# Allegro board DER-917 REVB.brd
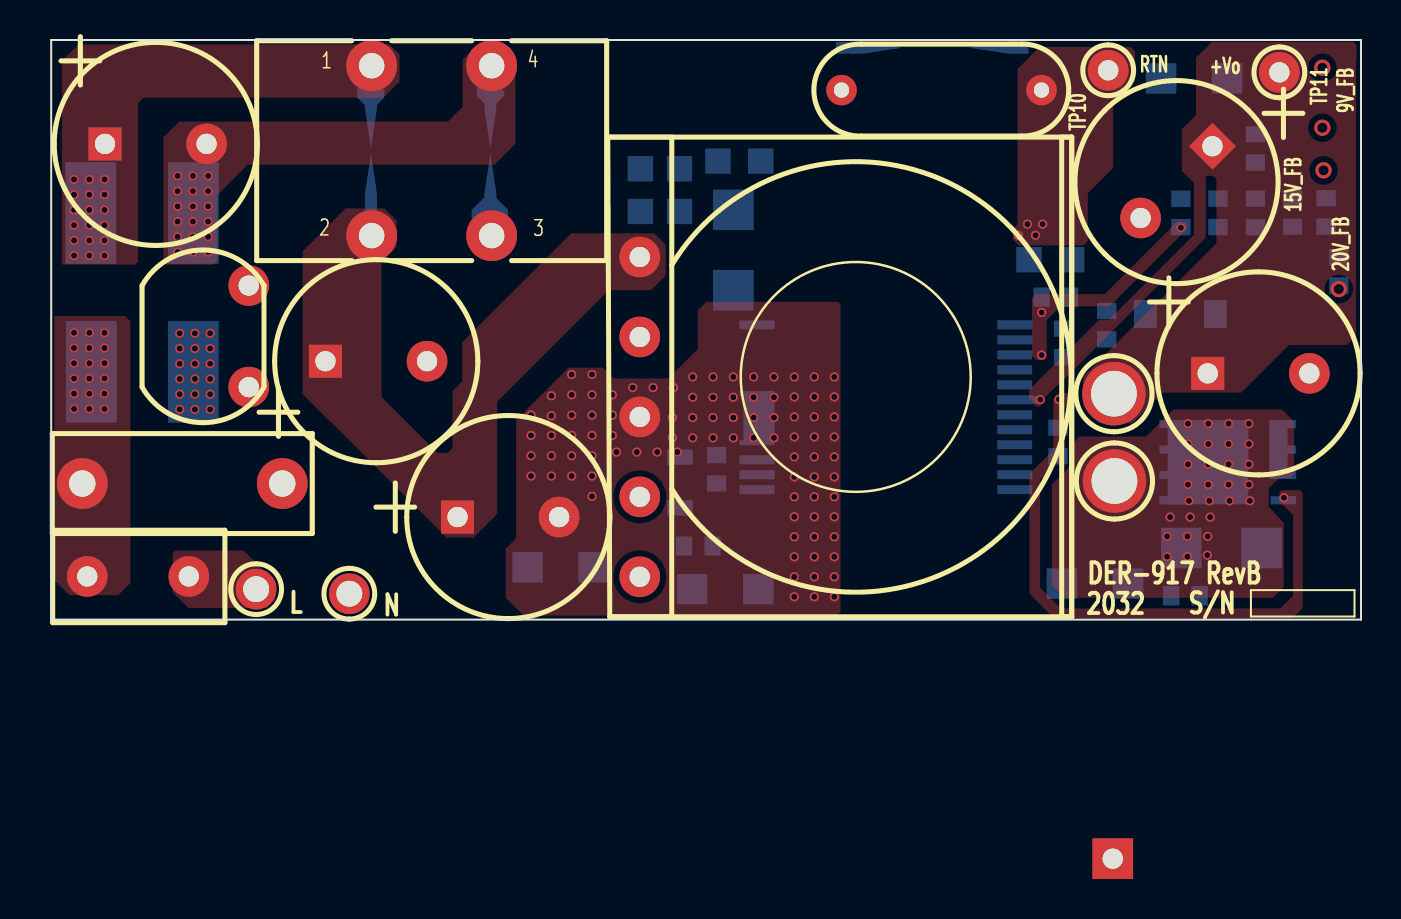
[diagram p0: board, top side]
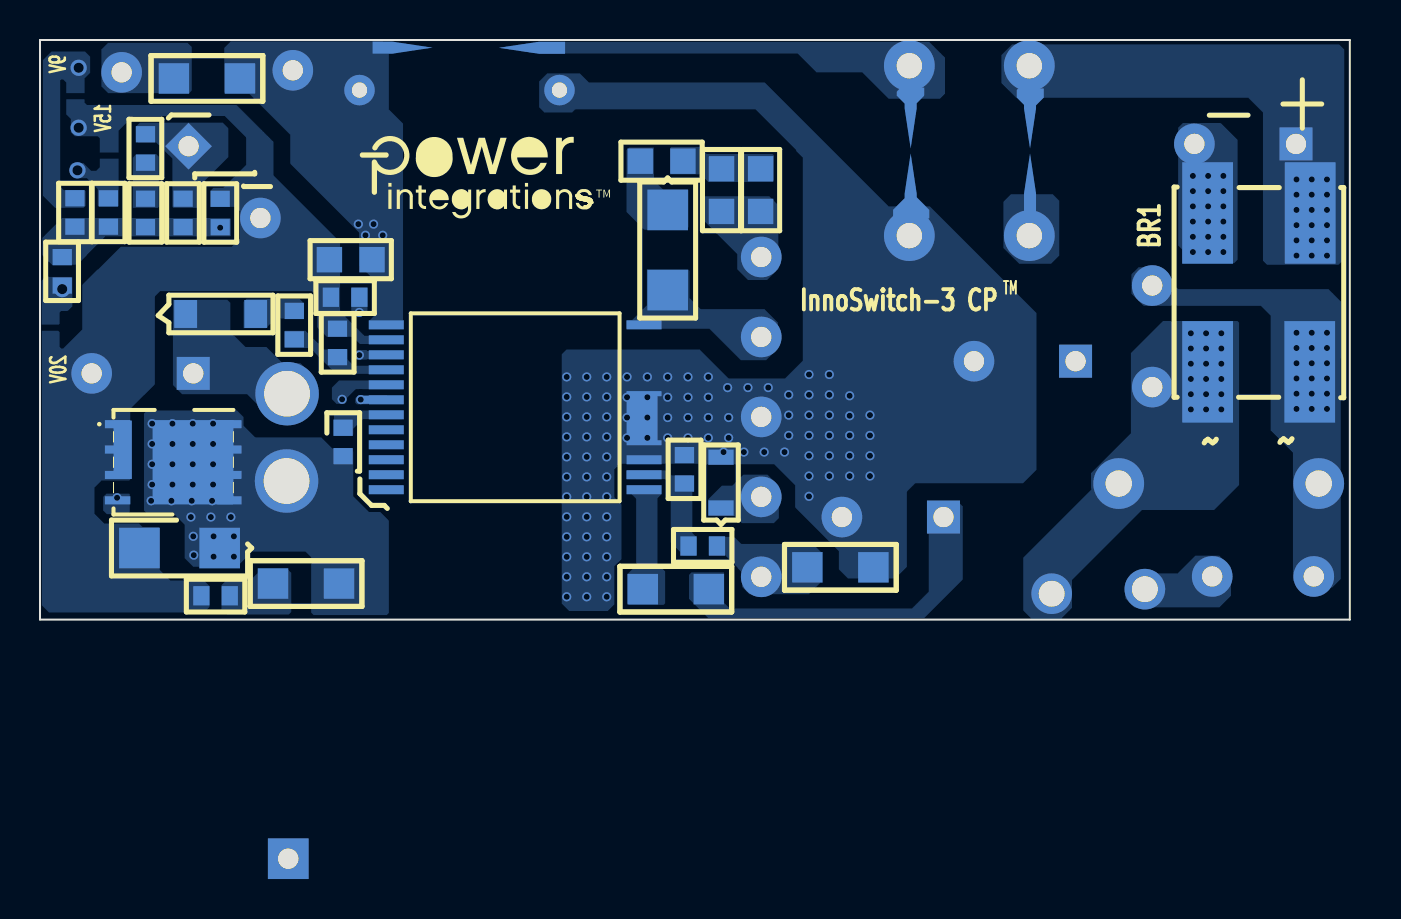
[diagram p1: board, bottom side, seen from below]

Outline 65.5 x 29 mm; copper layers: TOP, BOTTOM. Coordinates in mm from the lower left corner of the outline.
Outline path: 0,29 65.5,29 65.5,0 0,0 0,29

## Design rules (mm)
constraint set DEFAULT: min track width 0.508

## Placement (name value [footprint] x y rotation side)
BR1  Z4DGP406L-HF  [PI_SM_D_Z4D]  2.01 20.4 180 bottom
C1  0.1 uF  [PINPXCAPRAD5X13X11P1MM040]  11.56 6.81 180 top
C2  27 uF  [PIPOLCAPCYLD400LS200040]  20.32 5.13 0 top
C3  27 uF  [PIPOLCAPCYLD400LS200040]  13.72 12.93 0 top
C4  27 uF  [PIPOLCAPCYLD400LS200040]  2.69 23.8 0 top
C5  0.47 uF  [PISMC0603]  33.27 6.81 90 bottom
C6  10 uF  [PISMC1206]  27.13 2.62 180 bottom
C7  2200 pF  [PINPCAPRAD9P0D10P0LS030]  39.52 26.49 0 top
C8  2200 pF  [PISMC0603]  56.01 1.19 0 bottom
C9  2.2 uF  [PISMC0603]  50.62 13.13 90 bottom
C11  330 pF  [PISMC0603]  49.53 16.13 0 bottom
C12  47 nF  [PISMC0603]  60.22 21.06 270 bottom
C13  10 uF  [PISMC1206]  58.8 27.08 180 bottom
C14  390 uF  [PIPOLCAPCYLD400LS200040]  58.07 23.68 225 top
C15  390 uF  [PIPOLCAPCYLD400LS200040]  57.84 12.32 0 top
C18  470 pF  [PISMC0805]  29.46 20.42 90 bottom
D1  RS1J  [PISMDSMA]  34.11 20.5 270 bottom
D2  BAV21WS-7-F  [PISMSOD323]  31.45 5.59 90 bottom
D4  STPS2H100AY  [PISMDSMA]  56.52 3.58 0 bottom
F1  5 A  [PI_RST_MICROFUSE]  6.88 2.16 180 top
FL1  Hole_90  [PI_HOLE_70MIL]  53.14 11.28 0 top
FL2  Hole_90  [PI_HOLE_70MIL]  53.17 6.91 0 top
L1  18mH  [PI_CMC_18MH_SUMIDA]  16.03 27.71 0 top
NOREF  -  []  0 29 0 top
NOREF#2  -  []  -150.78 54.23 0 top
NOREF#3  -  []  65.5 0 90 top
NOREF#4  -  []  -228.6 -144.78 0 top
NOREF#5  -  []  49.43 23.95 180 bottom
Q3  SIR826ADP-T1-GE3  [PISMPQFN5X6B]  61.62 9.78 270 bottom
R5  30.1  [PISMR0805]  33.35 22.94 0 bottom
R8  24.9 k  [PISMR0603]  31.65 3.68 0 bottom
R10  47  [PISMR0603]  50.34 8.18 90 bottom
R13  0.0  [PISMR1206]  50.55 1.8 0 bottom
R14  100 k  [PISMR0603]  58.34 21.06 270 bottom
R15  33 K  [PISMR0603]  56.49 19.63 90 bottom
R16  0.005  [PISMR0805]  51.03 18.01 180 bottom
R19  2.2M  [PISMR1206]  35.36 1.52 180 bottom
R21  680 k  [PISMR0805]  31.42 20.42 90 bottom
R22  32.4 k  [PISMR0603]  63.75 19.66 90 bottom
R23  12.7 k  [PISMR0603]  62.08 19.66 90 bottom
R24  10 k  [PISMR0603]  60.22 24.28 270 bottom
R25  1.2 k  [PISMR0603]  52.78 15.44 270 bottom
R27  8.25 k  [PISMR0603]  64.39 18.14 270 bottom
RV1  175 Vac  [PI_DISC_335X240LS200D040]  9.88 11.63 90 top
T1  EQ25  [PI_BOBBIN_EQ-25_6P]  40.23 12.14 0 top
TP1  N  [PITPKEYSTONE100X100]  14.91 1.3 0 top
TP2  L  [PITPKEYSTONE100X100]  10.25 1.52 0 top
TP10  RTN  [PITPKEYSTONE100X100]  52.86 27.48 0 top
TP11  +Vo  [PITPKEYSTONE100X100]  61.42 27.38 0 top
U1  INN3270C-H203  [PI_IC_INSOP_24D]  48.18 14.75 180 bottom
VR1  MMSZ5250B-7-F  [PI_SM_SOD-123_12]  58.22 15.29 180 bottom

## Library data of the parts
BR1 = DISCRETE BRIDGE_+~~-
C1 = CAP NP: alternate symbols: (pinpxcaprad5x13x11p1mm040h)
C2-C4 = CAP POL: alternate symbols: (pipolcapclyd400x675ls200040h)
C5 C7-C9 C11-C13 C18 = CAP NP
C6 = CAP NP: alternate symbols: (pismc1206_1)
C14 C15 = CAP POL: alternate symbols: (pipolcapclyd400x530ls200030h)
D1 D2 = DIODE
D4 = DIODE SCHOTTKY
F1 = FUSE: alternate symbols: (pirstmicrofusehoz)
FL1 FL2 = FlyingLead
L1 = TORRID 4P_12_43a: alternate symbols: (pi_CMC_18mH_SumidaW,pi_CMC_18mH_Sumida_H)
Q3 = FET_N_SGD_123_4_5678
R5 R8 R10 R13-R16 R19 R21-R25 R27 = R
RV1 = VARISTOR
T1 = BEQ25_6P
TP1 TP2 TP10 TP11 = TESTPOINT
U1 = Inno3CP_P15
VR1 = DIODE_ZENER

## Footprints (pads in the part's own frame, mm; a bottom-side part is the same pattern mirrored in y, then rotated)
PI_BOBBIN_EQ-25_6P
  rect 2.032x2.032 hole 1.016: 1(12.852,-24.105)
  round 2.032 hole 1.016: 2(-10.8,6) 3(-10.8,2) 4(-10.8,-2) 5(-10.8,-6) 6(-10.8,-10)
PI_CMC_18MH_SUMIDA
  round 2.54 hole 1.27: 1(0,0) 2(0,-8.5) 3(6,-8.5) 4(6,0)
PI_DISC_335X240LS200D040
  round 2.032 hole 1.016: 1(0,0) 2(5.08,0)
PI_HOLE_70MIL
  round 3.175 hole 2.286: 1(0,0.025)
PI_IC_INSOP_24D
  rect 1.75x0.45 smd: 1(0,0) 2(0,-0.75) 3(0,-1.5) 4(0,-2.25) 5(0,-3) 6(0,-3.75) 7(0,-4.5) 8(0,-5.25) 9(0,-6) 10(0,-6.75) 11(0,-7.5) 12(0,-8.25) 13(12.89,-8.25) 14(12.89,-7.5) 15(12.89,-6.75) 24(12.89,0)
  custom 0.438x0.438 smd: 16(12.89,-4.67)
PI_RST_MICROFUSE
  round 2.032 hole 1.016: 1(0,0) 2(5.08,0)
PI_SM_D_Z4D
  rect 2.54x5.08 smd: 1(0.025,-0.051) 2(0,-8.001) 3(-5.105,-8.001) 4(-5.105,-0.051)
PI_SM_SOD-123_12
  rect 1.143x1.397 smd: 1(0,0) 2(3.505,0)
PINPCAPRAD9P0D10P0LS030
  round 1.524 hole 0.762: 1(0,0) 2(10,0)
PINPXCAPRAD5X13X11P1MM040
  round 2.54 hole 1.321: 1(0,0) 2(10,0)
PIPOLCAPCYLD400LS200040
  rect 1.651x1.651 hole 1.016: 1(0,0)
  round 2.032 hole 1.016: 2(5.08,0)
PISMC0603
  rect 0.813x0.965 smd: 1(0,0) 2(1.422,0)
PISMC0805
  rect 1.27x1.27 smd: 1(0,0) 2(2.134,0)
PISMC1206
  rect 1.524x1.524 smd: 1(0,0) 2(3.302,0)
PISMDSMA
  rect 2.032x2.032 smd: 1(0,0) 2(4.013,0)
PISMPQFN5X6B
  rect 0.406x1.27 smd: 1(0,0) 2(1.27,0) 3(2.54,0) 4(3.81,0)
  rect 0.406x1.219 smd: 5(3.81,5.588) 6(2.54,5.588) 7(1.27,5.588) 8(0,5.588)
PISMR0603
  rect 0.813x0.965 smd: 1(0,0) 2(1.422,0)
PISMR0805
  rect 1.27x1.27 smd: 1(0,0) 2(2.134,0)
PISMR1206
  rect 1.524x1.524 smd: 1(0,0) 2(3.302,0)
PISMSOD323
  rect 0.762x1.27 smd: 1(0,0) 2(2.54,0)
PITPKEYSTONE100X100
  round 2.032 hole 1.295: 1(0,0)

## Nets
GND_POWER: C8.2 C9.2 C11.2 C14.2 C15.2 D4.2 Q3.1 Q3.2 Q3.3(S3) R15.2 R16.1 U1.2
GND_SIGNAL: C2.2 C3.2 C5.2 C6.2 C7.1 D2.2 L1.3 T1.4 U1.15 U1.16
NC8: U1.8
NC9: U1.9
NC10: U1.10
NC11: U1.11
NC12: U1.12
N11018979: C13.1 C14.1 C15.1 FL1.1 R14.1 R24.1 TP11.1 U1.6 VR1.1
N11018991: C7.2 C13.2 R16.2 TP10.1 U1.1
N11019023: R10.2 U1.7
N11019027: D4.1 FL2.1 Q3.5 Q3.6 Q3.7 Q3.8 R10.1 R13.1
N11019153: D1.1 R5.2
N11019263: BR1.4 C4.2 L1.4
N11019293: C5.1 R8.2 U1.14
N11019397: BR1.3(AC2) C1.1 RV1.1 TP1.1
N11019401: C8.1 R13.2
N11019613: C2.1 C3.1 C18.1 L1.2 R19.2 R21.1 T1.2
N11019673: BR1.2 C1.2 F1.2 RV1.2
N11019681: BR1.1 C4.1 L1.1
N11019743: C11.1 C12.2 R14.2 R15.1 R22.1 R23.1 R27.1 U1.3
N11020702: C18.2 R5.1 R21.2
N11020753: D1.2 T1.3 U1.24
N11026403: F1.1 TP2.1
N11096846: R22.2
N11102317: R23.2
N11111738: C12.1 R24.2
N11114484: R25.1 VR1.2
N12700264: R27.2
N12705759: D2.1 T1.5
N12705920: C6.1 R8.1 T1.6
N12717194: R19.1 U1.13(VPIN)
N12724298: Q3.4 U1.5
N12728725: C9.1 R25.2 U1.4

Pads without a net: T1 1

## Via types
v1: diameter 0.813, hole 0.508, TOP to BOTTOM, 4 vias
v2: diameter 0.457, hole 0.305, TOP to BOTTOM, 201 vias

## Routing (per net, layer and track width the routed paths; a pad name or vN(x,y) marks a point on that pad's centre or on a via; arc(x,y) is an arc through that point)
GND_POWER:
  vias: v1(63.57,24.61)
GND_SIGNAL:
  vias: v2(24,10.23) v2(24,9.21) v2(24,8.2) v2(24,7.18) v2(25.01,11.2) v2(25.01,10.2) v2(25.01,9.21) v2(25.01,8.2) v2(25.01,7.18) v2(26.03,12.26) v2(26.03,11.25) v2(26.03,10.23) v2(26.03,9.21) v2(26.03,8.2) v2(26.03,7.18) v2(27.04,12.26) v2(27.04,11.25) v2(27.04,10.23) v2(27.04,9.21) v2(27.04,8.2) v2(27.04,7.18) v2(27.04,6.17) v2(28.06,11.25) v2(28.06,10.23) v2(28.06,9.21) v2(28.27,8.38) v2(29.08,11.61) v2(29.29,8.38) v2(30.1,11.61) v2(30.3,8.38) v2(31.11,11.61) v2(31.06,10.11) v2(31.06,9.09) v2(31.32,8.38) v2(32.08,12.14) v2(32.08,11.13) v2(32.08,10.11) v2(32.08,9.09) v2(33.1,12.14) v2(33.1,11.13) v2(33.1,10.11) v2(33.1,9.09) v2(34.11,12.14) v2(34.11,11.13) v2(34.11,10.11) v2(34.11,9.09) v2(35.13,12.14) v2(35.13,11.13) v2(35.13,10.11) v2(35.13,9.09) v2(36.14,12.14) v2(36.14,11.13) v2(36.14,10.11) v2(36.14,9.09) v2(37.16,12.14) v2(37.16,11.14) v2(37.16,10.14) v2(37.16,9.14) v2(37.16,8.14) v2(37.16,7.14) v2(37.16,6.14) v2(37.16,5.14) v2(37.16,4.14) v2(37.16,3.14) v2(37.16,2.14) v2(37.16,1.14) v2(38.16,12.14) v2(38.16,11.14) v2(38.16,10.14) v2(38.16,9.14) v2(38.16,8.14) v2(38.16,7.14) v2(38.16,6.14) v2(38.16,5.14) v2(38.16,4.14) v2(38.16,3.14) v2(38.16,2.14) v2(38.16,1.14) v2(39.16,12.14) v2(39.16,11.14) v2(39.16,10.14) v2(39.16,9.14) v2(39.16,8.14) v2(39.16,7.14) v2(39.16,6.14) v2(39.16,5.14) v2(39.16,4.14) v2(39.16,3.14) v2(39.16,2.14) v2(39.16,1.14)
N11018979: length 1.3
  BOTTOM w0.4: v2(49.46,11.01) 49.45,11 U1.6
N11018991:
  vias: v2(48.36,19.23) v2(48.82,19.79) v2(49.23,19.23) v2(49.58,19.79)
N11019027:
  vias: v2(55.8,4.17) v2(55.8,3.15) v2(55.96,5.13) v2(56.85,9.8) v2(56.85,8.79) v2(56.85,7.77) v2(56.85,6.76) v2(56.82,4.17) v2(56.82,3.15) v2(56.9,5.94) v2(56.96,5.13) v2(57.84,4.17) v2(57.81,3.23) v2(57.86,9.8) v2(57.86,8.79) v2(57.86,7.77) v2(57.86,6.76) v2(57.91,5.94) v2(57.96,5.13) v2(58.88,9.8) v2(58.88,8.79) v2(58.88,7.77) v2(58.88,6.76) v2(58.93,5.94) v2(59.89,9.8) v2(59.89,8.79) v2(59.89,7.77) v2(59.89,6.76) v2(59.94,5.94)
N11019263:
  vias: v2(6.32,22.2) v2(6.32,21.44) v2(6.32,20.68) v2(6.32,19.91) v2(6.32,19.15) v2(6.32,18.39) v2(7.09,22.2) v2(7.09,21.44) v2(7.09,20.68) v2(7.09,19.91) v2(7.09,19.15) v2(7.09,18.39) v2(7.85,22.2) v2(7.85,21.44) v2(7.85,20.68) v2(7.85,19.91) v2(7.85,19.15) v2(7.85,18.39)
N11019397:
  vias: v2(6.43,14.33) v2(6.43,13.56) v2(6.43,12.8) v2(6.43,12.04) v2(6.43,11.28) v2(6.43,10.52) v2(7.19,14.33) v2(7.19,13.56) v2(7.19,12.8) v2(7.19,12.04) v2(7.19,11.28) v2(7.19,10.52) v2(7.95,14.33) v2(7.95,13.56) v2(7.95,12.8) v2(7.95,12.04) v2(7.95,11.28) v2(7.95,10.52)
N11019673:
  vias: v2(1.14,14.35) v2(1.14,13.59) v2(1.14,12.83) v2(1.14,12.06) v2(1.14,11.3) v2(1.14,10.54) v2(1.91,14.35) v2(1.91,13.59) v2(1.91,12.83) v2(1.91,12.06) v2(1.91,11.3) v2(1.91,10.54) v2(2.67,14.35) v2(2.67,13.59) v2(2.67,12.83) v2(2.67,12.06) v2(2.67,11.3) v2(2.67,10.54)
N11019681:
  vias: v2(1.14,22.02) v2(1.14,21.26) v2(1.14,20.5) v2(1.14,19.74) v2(1.14,18.97) v2(1.14,18.21) v2(1.91,22.02) v2(1.91,21.26) v2(1.91,20.5) v2(1.91,19.74) v2(1.91,18.97) v2(1.91,18.21) v2(2.67,22.02) v2(2.67,21.26) v2(2.67,20.5) v2(2.67,19.74) v2(2.67,18.97) v2(2.67,18.21)
N11019743:
  vias: v2(49.53,15.37) v2(49.53,13.23) v2(56.49,19.61)
N11096846:
  vias: v1(63.57,27.61)
N11102317:
  vias: v1(63.63,22.48)
N12700264:
  vias: v1(64.39,16.54)
N12724298:
  vias: v2(50.39,11.02) v2(61.65,6.1)
N12728725: length 0.1
  BOTTOM w0.254: 52.7,14.02 R25.2

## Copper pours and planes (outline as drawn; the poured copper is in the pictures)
GND_POWER on BOTTOM (solid shape): 61.82,7.04 60.91,7.04 60.91,9.96 61.82,9.96
GND_POWER on BOTTOM: 62.78,6.6 62.42,6.96 61.04,6.96 60.99,7.01 60.99,10.54 59.75,11.77 59.75,16.17 59.49,16.43 51.92,16.43 51.64,16.15 51.64,14.63 51.16,14.15 49.86,14.15 49.5,13.79 47.42,13.79 47.37,13.84 47.37,14.15 47.42,14.2 49.28,14.2 50.5,15.42 50.5,18.9 53.82,22.23 53.82,23.9 55.66,25.74 63.14,25.74 63.27,25.87 63.27,26.04 64.19,26.04 64.19,25.27 63.96,25.04 63.96,24.38 63.75,24.18 62.61,24.18 62.51,24.08 62.51,23.37 61.57,23.37 61.57,24.46 60.83,25.2 56.26,25.2 55.19,24.13 55.19,22.75 56.34,21.6 56.83,21.6 56.92,21.51 56.92,20.75 56.82,20.65 55.7,20.65 55.5,20.45 55.5,19.06 55.91,18.66 61.46,18.66 62.59,17.53 62.61,17.53 63.39,16.75 63.39,14.52 64.34,13.56 64.44,13.56 64.52,13.64 64.52,14.38 64.59,14.45 65.41,14.45 65.41,0.71 65.05,0.36 57.61,0.36 57.58,0.33 57.33,0.33 57.02,0.64 57.02,1.68 57.3,1.96 58.98,1.96 59.51,2.49 59.51,4.57 59.56,4.62 60.36,4.62 60.55,4.81 62.29,4.81 62.78,5.3
GND_SIGNAL on BOTTOM (solid shape): 22.26,21.32 22.26,21.08 22.84,20.5 22.84,20.07 21.03,20.07 21.03,20.5 21.66,21.13 21.66,21.32 21.96,23.32
GND_SIGNAL on TOP: 39.47,0.38 39.29,0.2 23.62,0.2 22.73,1.09 22.73,3.56 23.25,4.08 23.25,9.98 25.88,12.61 27.57,12.61 28.12,12.06 30.86,12.06 32.31,13.51 32.33,13.51 32.33,15.47 32.77,15.9 39.34,15.9 39.47,15.77
GND_SIGNAL on BOTTOM: 28.24,12.06 31.06,12.06 32.51,13.51 39.17,13.51 39.41,13.27 39.41,0.8 39.04,0.43 37.11,0.43 36.78,0.76 36.78,2.67 36.42,3.02 36.42,5.77 36.78,6.12 36.78,7.52 36.5,7.8 32.59,7.8 32.56,7.77 28.79,7.77 27.74,6.72 27.74,5.61 25.55,3.43 25.55,2.51 25.1,2.06 22.73,2.06 22.15,2.64 22.15,6.4 21.73,6.82 16.34,6.82 15.67,7.49 15.67,15.34 21.01,20.68 23.06,20.68 29.26,26.87 38.05,26.87 38.51,27.33 40.13,27.33 40.54,26.92 40.54,25.63 40.28,25.37 38.89,25.37 38.73,25.53 29.72,25.53 27.69,23.5 27.69,23.44 27.36,23.11 27.36,12.95
N11018979 on TOP: 58.04,28.91 65.1,28.91 65.28,28.73 65.28,28.09 65.25,28.07 65.25,14.2 64.8,13.74 61.9,13.74 59.51,11.35 55.6,11.35 54.08,9.83 52.45,9.83 51.61,10.67 51.61,12.17 58.27,18.82 58.27,22.05 58.12,22.2 57.81,22.2 57.73,22.12 57.73,19.1 50.37,11.73 50.32,11.73 49.68,11.1 49.68,10.9 49.45,10.67 49.28,10.67 48.9,11.05 48.9,11.48 52.43,15.01 52.91,15.01 57.15,19.25 57.15,21.84 56.54,22.45 56.54,24.54 57.25,25.25 57.25,28.12
N11018979 on BOTTOM: 52.48,12.83 53.37,12.83 54.18,13.64 55.22,13.64 55.98,14.4 55.98,15.85 56.13,16 58.85,16 58.85,11.73 58.39,11.28 55.14,11.28 53.87,10.01 52.55,10.01 51.79,10.77 51.79,12.14
N11018979 on BOTTOM: 47.32,11.2 49.05,11.2 49.07,11.23 49.58,11.23 49.73,11.07 49.73,10.85 49.66,10.77 49.1,10.77 49.07,10.79 47.32,10.79
N11018979 on BOTTOM: 57.91,26.47 58.04,26.34 62.09,26.34 62.43,26.68 62.43,28.52 62.1,28.85 58.12,28.85 57.91,28.65
N11018979 on BOTTOM: 56.34,24.87 60.5,24.87 60.71,24.66 60.71,24 60.58,23.88 59.69,23.88 58.88,23.06 58.88,20.65 58.83,20.6 57.61,20.6 57.56,20.65 57.56,21.67 56.08,23.14 56.08,24.61
N11018991 on BOTTOM (solid shape): 48.87,28.32 47.87,28.32 45.87,28.62 47.87,28.92 48.87,28.92
N11018991 on TOP: 49.43,28.65 48.32,27.55 48.32,19.77 48.09,19.55 48.09,19 48.11,19 48.39,18.72 51.61,18.72 51.84,18.95 51.84,21.34 53.11,22.61 53.11,25.86 54.2,26.95 54.2,28.42 53.98,28.65
N11018991 on BOTTOM: 47.35,24.82 48.06,25.53 48.06,28.63 48.36,28.93 55.96,28.93 56.29,28.6 56.29,26.39 56.21,26.31 55.04,26.31 52.98,24.26 52.98,22.81 49.54,19.37 49.54,17.74 48.74,16.94 48.74,15.24 49.03,14.95 49.03,14.53 47.55,14.53 47.35,14.73
N11019023 on BOTTOM: 47.32,10.46 50.6,10.46 50.8,10.26 50.8,9.22 50.77,9.19 49.91,9.19 49.83,9.27 49.83,9.55 49.35,10.03 47.4,10.03 47.32,10.11
N11019027 on BOTTOM (solid shape): 59.87,5.77 55.83,5.77 55.83,9.98 59.87,9.98
N11019027 on TOP: 50.04,6.76 50.04,1.73 50.67,1.09 61.09,1.09 61.63,1.64 61.63,4.86 61.14,5.36 61.14,5.38 60.88,5.64 60.88,6.58 61.39,7.09 61.95,7.09 62.15,7.29 62.15,9.91 61.54,10.52 56.11,10.52 54.75,9.16 51.42,9.16 51.13,8.86 51.13,7.85
N11019027 on BOTTOM: 51.44,9.12 50.88,8.56 49.99,8.56 49.83,8.41 49.83,6.17 49.05,5.38 48.49,5.38 48.06,4.95 48.06,0.33 48.16,0.23 51.82,0.23 51.94,0.36 51.94,3.12 52.22,3.4 54.89,3.4 55.65,2.64 57.84,2.64 58.27,3.07 58.27,4.75 58.83,5.31 60.15,5.31 60.3,5.46 60.3,10.31 60.15,10.46 55.65,10.46 55.32,10.13 55.32,9.7 54.74,9.12
N11019153 on BOTTOM: 33.1,21.51 34.34,21.51 34.8,21.97 34.8,23.62 36.04,23.62 36.17,23.5 36.17,20.4 35.28,19.51 33.2,19.51 33.07,19.63 33.07,21.49
N11019263 on BOTTOM (solid shape): 42.55,28.61 40.55,28.31 40.57,28.31 39.26,28.31 39.24,28.32 39.24,28.91 39.25,28.91 40.55,28.91
N11019263 on BOTTOM (solid shape): 22.66,26.42 22.66,26.21 22.26,25.82 22.26,25.57 21.96,23.57 21.66,25.57 21.66,25.83 21.29,26.21 21.29,26.62 21.46,26.62 21.49,26.64 22.43,26.64
N11019263 on TOP: 19.84,24.92 20.57,25.65 20.57,28.02 21.41,28.85 22.48,28.85 23.22,28.12 23.22,23.8 22.17,22.76 9.83,22.76 8.28,21.21 8.28,17.93 8.1,17.75 5.74,17.75 5.61,17.88 5.61,24.13 6.4,24.92
N11019263 on BOTTOM: 23.06,26.06 20.5,26.06 20.24,26.31 20.24,28.12 21.03,28.91 40.06,28.91 40.16,28.8 40.16,28.35 40.13,28.32 27.61,28.32 26.67,27.38 24.38,27.38
N11019263 on BOTTOM: 5.61,18.01 5.61,24 6.45,24.84 8.36,24.84 8.59,24.61 8.59,18.72 8.38,18.52 8.38,17.83 5.79,17.83
N11019293 on BOTTOM: 36.17,7.47 36.17,7.04 34.26,7.04 33.96,6.73 33.96,3.86 33.3,3.2 32.69,3.2 32.66,3.23 32.66,4.11 32.88,4.33 32.88,7.18 32.92,7.21 33.91,7.21 34.16,7.47
N11019397 on BOTTOM: 10.39,5.49 13.89,1.98 13.89,0.58 14.43,0.05 15.93,0.05 16.33,0.46 16.33,3.1 12.93,6.5 12.93,6.55 12.94,6.57 12.94,7.33 10.95,9.32 10.95,13.34 9.35,14.94 5.61,14.94 5.54,14.86 5.54,6.73 6.78,5.49
N11019401 on BOTTOM: 52.93,2.34 52.93,0.38 53.06,0.25 56.18,0.25 56.43,0.5 56.43,1.71 56.21,1.93 55.02,1.93 54.41,2.54 53.14,2.54
N11019613 on BOTTOM (solid shape): 16.29,21.32 16.29,20.32 15.69,20.32 15.69,21.32 15.99,23.32
N11019613 on TOP: 14.73,20.57 16.66,20.57 17.27,19.96 17.27,18.64 16.51,17.88 16.51,11.15 19.32,8.34 19.82,8.34 20.07,8.59 20.07,11.43 20.56,11.93 20.56,13.88 26.01,19.33 30.15,19.33 30.73,18.75 30.73,17.22 30,16.48 27.89,16.48 22.3,10.9 22.3,5.28 21.16,4.14 21.16,4.11 19.76,4.11 13.97,9.91 13.94,9.91 12.57,11.28 12.57,18.41
N11019613 on BOTTOM: 14.94,17.81 16.54,17.81 17.32,18.59 17.32,20.83 17.32,20.9 16.94,21.29 14.86,21.29 14.53,20.95 14.53,18.21
N11019613 on BOTTOM: 32.92,2.36 33.05,2.24 33.05,1.04 32.08,0.08 21.29,0.08 19.35,2.01 19.35,5.66 19.61,5.92 20.9,5.92 21.06,5.77 21.06,1.4 21.89,0.56 30.81,0.56 30.82,0.57 31.03,0.57 31.29,0.84 31.29,2.36
N11019613 on BOTTOM: 28.57,17.55 28.57,20.73 29.03,21.18 32.23,21.18 32.28,21.13 32.28,19.94 30.63,18.29 30.63,17.53 30.1,16.99 29.13,16.99
N11019673 on TOP: 0.15,15.19 3.71,15.19 3.96,14.94 3.96,1.83 3.35,1.22 0.91,1.22 0.15,1.98
N11019673 on BOTTOM: 0.46,2.03 0.89,1.6 2.49,1.6 2.84,1.96 2.84,8.36 3.96,9.47 3.96,15.21 4.45,15.7 10.31,15.7 10.92,16.31 10.92,17.27 10.57,17.63 9.47,17.63 8.89,17.04 8.89,16.84 8.59,16.54 1.07,16.54 0.43,15.9 0.43,13.08 0.46,13.06
N11019681 on BOTTOM (solid shape): 16.66,26.5 16.66,26.12 16.29,25.76 16.29,25.57 15.99,23.57 15.69,25.57 15.69,25.73 15.3,26.12 15.3,26.57 16.58,26.57
N11019681 on TOP: 0.53,17.81 0.53,27.94 1.37,28.78 16.92,28.78 17.42,28.27 17.42,26.92 16.61,26.11 4.62,26.11 4.34,25.83 4.34,17.91 4.19,17.75 0.58,17.75
N11019681 on BOTTOM: 16.89,28.78 17.42,28.24 17.42,26.85 16.69,26.11 5.08,26.11 4.34,25.37 4.34,17.96 4.14,17.75 0.56,17.75 0.28,18.03 0.28,28.52 0.53,28.78
N11019743 on TOP: 49.05,13.21 49.05,16.1 49.23,16.28 52.68,16.28 56.31,19.91 56.67,19.91 56.79,19.79 56.79,19.53 52.93,15.67 50.47,15.67 49.78,14.99 49.78,13.11 49.66,12.98 49.28,12.98
N11019743 on BOTTOM: 56.01,20.09 64.39,20.09 65.38,19.1 65.38,18.24 64.9,17.75 63.63,17.75 63.17,18.21 63.17,18.24 62.23,19.18 55.98,19.18 55.96,19.2 55.96,20.04
N11019743 on BOTTOM: 49.12,16.56 49.12,15.44 49.43,15.14 49.63,15.14 49.94,15.44 49.94,16.56
N11019743 on BOTTOM: 47.35,13.44 49.12,13.44 49.17,13.49 49.63,13.49 49.78,13.34 49.78,13.11 49.68,13 49.17,13 49.15,13.03 47.32,13.03 47.32,13.41
N11020702 on BOTTOM: 28.85,23.29 32.16,23.29 32.51,23.65 33.93,23.65 33.99,23.6 33.99,22.28 32.46,22.28 32.08,21.89 28.91,21.89 28.8,22 28.8,23.24
N11020753 on BOTTOM: 36.17,14.55 36.17,14.99 35.89,14.99 35.15,15.72 35.15,17.53 33.1,17.53 33.02,17.45 33.02,16.09 32.46,15.53 29.27,15.53 28.6,14.86 28.6,13.56 29.18,12.98 30.45,12.98 32.03,14.55
N11026403 on TOP: 10.79,0.58 11.2,0.99 11.2,1.88 9.63,3.45 6.22,3.45 6.07,3.3 6.07,1.37 6.86,0.58
N11026403 on BOTTOM: 10.74,2.31 8.61,2.31 7.72,3.2 6.53,3.2 5.94,2.62 5.94,1.19 6.53,0.61 10.77,0.61 11.23,1.07 11.23,1.83
N11096846 on BOTTOM: 63.27,27.08 62.99,27.36 62.99,28.17 63.25,28.42 64.92,28.42 65.35,27.99 65.35,21.21 64.74,20.6 63.32,20.6 63.22,20.7 63.22,21.44 63.27,21.49 64.31,21.49 64.49,21.67 64.49,26.97 64.44,27.03 64.34,27.03 64.19,26.87 64.19,26.34 63.27,26.34
N11102317 on BOTTOM: 61.57,23.06 62.51,23.06 62.51,22.63 62.69,22.45 62.94,22.45 63.32,22.83 63.88,22.83 63.98,22.73 63.98,22.28 63.79,22.09 63.16,22.09 62.61,21.54 62.61,20.73 62.56,20.68 62.56,20.65 61.62,20.65 61.57,20.7
N11111738 on BOTTOM: 59.69,23.29 60.68,23.29 60.86,23.11 60.86,20.6 59.61,20.6 59.56,20.65 59.56,23.16
N11114484 on BOTTOM: 52.53,16.05 55.17,16.05 55.32,15.9 55.32,14.58 54.2,14.58 53.72,15.06 52.3,15.06 52.3,15.8 52.29,15.81
N12700264 on BOTTOM: 63.91,17.14 65.23,17.14 65.42,16.95 65.42,14.77 65.41,14.76 64.57,14.76 64.52,14.81 64.52,15.37 64.44,15.44 64.11,15.44 63.88,15.67 63.88,17.12
N12705759 on BOTTOM: 32.08,5.18 30.76,5.18 30.4,4.83 28.8,4.83 28.55,5.08 28.55,6.68 29.12,7.25 30.33,7.25 30.87,6.71 31.39,6.71 32.08,6.02
N12705920 on BOTTOM: 30.61,2.59 30.61,2.57 30.39,2.35 30.39,1.64 30.02,1.27 27.05,1.27 26.42,1.91 26.42,3.35 26.85,3.78 30.43,3.78 30.78,4.14 32,4.14 32,3.38 31.85,3.23 31.24,3.23
N12717194 on BOTTOM: 34.44,6.71 35.97,6.71 36.09,6.58 36.09,6.45 35.69,6.05 35.69,2.72 36.12,2.29 36.12,0.81 36.04,0.74 34.32,0.74 34.24,0.81 34.24,2.41 34.62,2.79 34.62,6.07 34.44,6.25
N12724298 on TOP: 61.42,5.89 61.42,6.38 61.52,6.48 62.46,6.48 62.59,6.35 62.59,0.58 62.08,0.08 50.14,0.08 48.92,1.3 48.92,7.29 50.11,8.48 50.11,11.02 50.42,11.33 50.9,11.33 51.03,11.2 51.03,10.95 50.67,10.59 50.67,8.2 49.45,6.99 49.45,1.6 50.5,0.56 61.47,0.56 62.1,1.19 62.1,5.23 61.59,5.74 61.57,5.74
N12724298 on BOTTOM: 47.4,11.96 50.55,11.96 50.9,11.61 50.9,11.02 50.67,10.79 50.27,10.79 50.18,10.88 50.18,11.06 49.71,11.53 47.47,11.53 47.35,11.66 47.35,11.91
N12724298 on BOTTOM: 61.04,6.3 62.18,6.3 62.34,6.13 62.34,5.46 62.16,5.28 61.12,5.28 61.01,5.38 61.01,6.27
N12728725 on BOTTOM: 47.4,12.7 49.81,12.7 50.14,13.03 50.14,13.51 51.28,13.51 52.22,14.45 53.24,14.45 53.29,14.4 53.29,13.64 53.24,13.59 51.99,13.59 50.7,12.29 47.4,12.29 47.37,12.27 47.35,12.29 47.35,12.65

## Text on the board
Ref Des/Silkscreen Bottom: TM | 15V | 20V | 9V | InnoSwitch-3 CP
User.Comments: 10 | 13 | /16 | 25 | 20 | NG | 7
Ref Des/Silkscreen Top: RTN | +Vo | TP10 | 15V_FB | TP11 | 20V_FB | 9V_FB | L | N | 2032 | DER-917 RevB | S/N
User.6: 14.  FAB HOUSE LOGO,DATE CODE TO BE IN SILK SCREEN ONLY.DO NOT USE COPPER. | 13.  MATERIAL FR4 COPPER 2oz THICKNESS 0.062"
User.8: FIGURE | FINISHED_SIZE | 12.0 | 20.0 | 40.0 | 50.0 | 51.0 | 52.0 | 90.0 | DRILL CHART: TOP to BOTTOM | ALL UNITS ARE IN MILS | PLATED | QTY | 202 | 4 | 22 | 2
